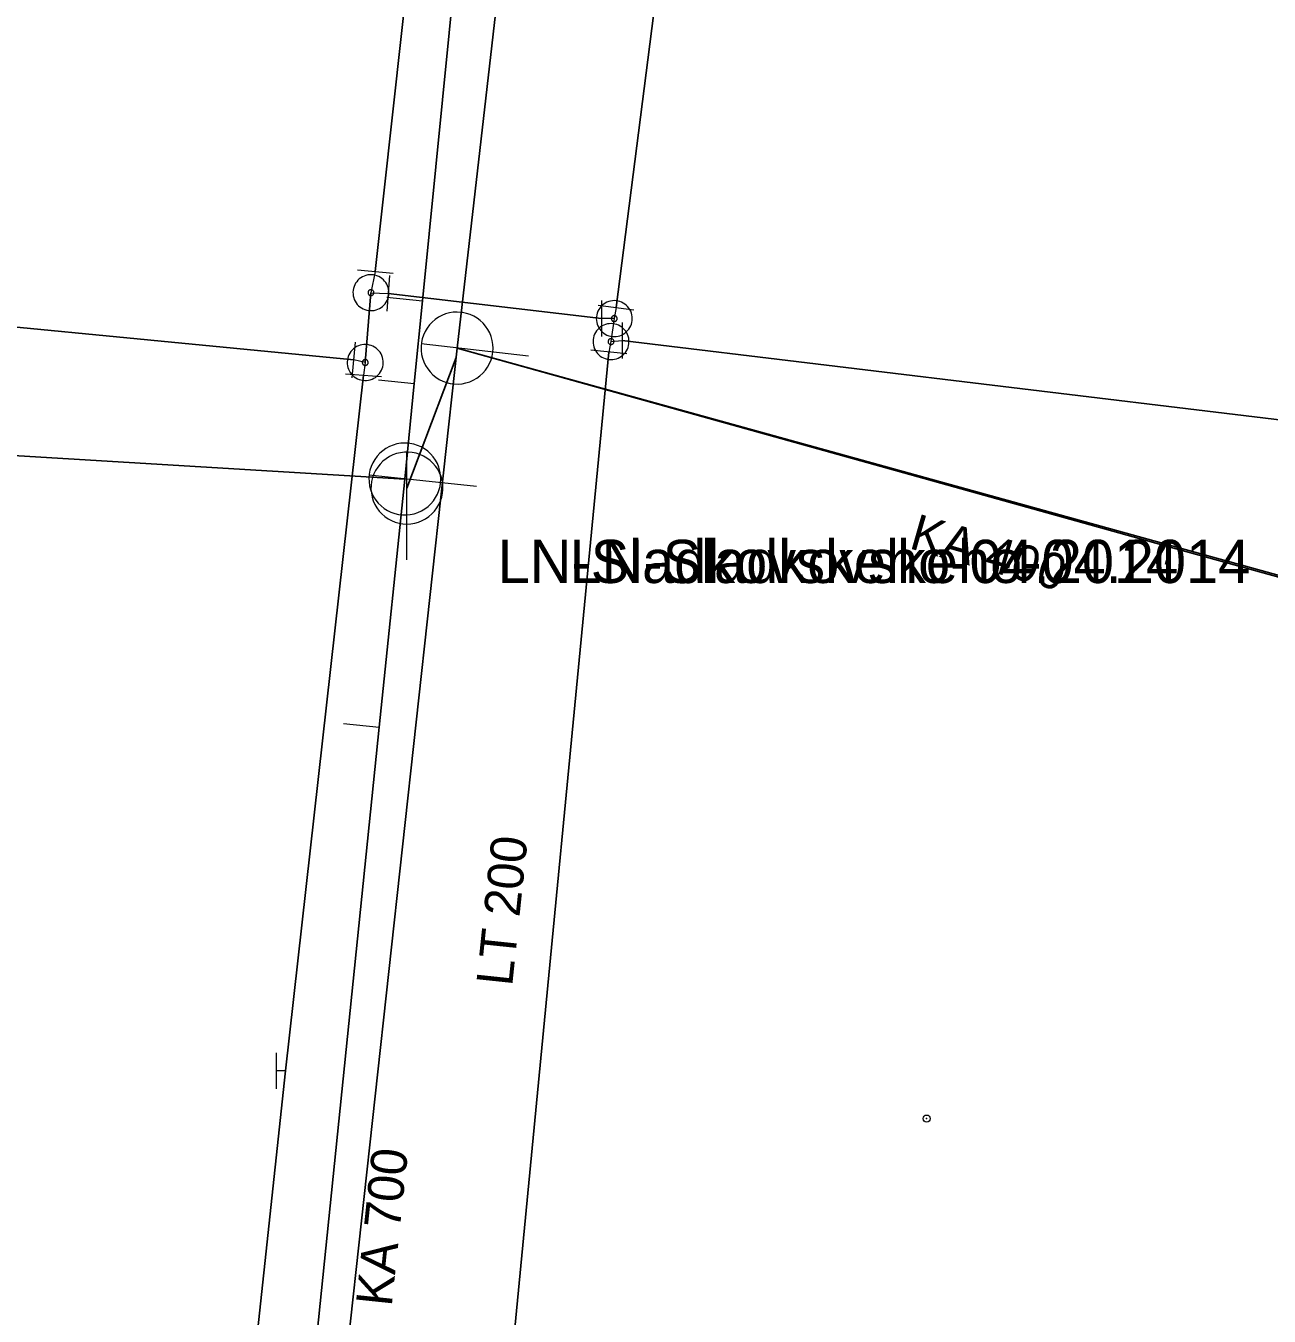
# Model space of a CAD drawing. Extents: x -783064 to -782702, y -1007904 to -1007145.
# Drawn here: x -782810.93 to -782776.38, y -1007591.58 to -1007555.71 of the extents above; entities that cross this region are included whole.
import ezdxf

# ---------------------------------------------------------------- set-up
doc = ezdxf.new("R2010")
doc.units = 0
doc.header["$LTSCALE"] = 0.4
doc.header["$PDMODE"] = 32
doc.header["$PDSIZE"] = 0.2
for name, color, linetype, lineweight in [('1', 7, 'Continuous', 13), ('11', 7, 'Continuous', 13), ('14', 7, 'Continuous', 13), ('17', 7, 'Continuous', 25), ('22', 7, 'Continuous', 13), ('34', 7, 'Continuous', 13), ('47', 7, 'Continuous', 13)]:
    doc.layers.add(name, color=color, linetype=linetype, lineweight=lineweight)

msp = doc.modelspace()

# ---------------------------------------------------------------- linework, layer by layer
at = {"layer": '1'}
msp.add_point((-782785.899, -1007586.089), dxfattribs=at)
at = {"layer": '11'}
for p, q in [((-782800.901, -1007563.255), (-782799.905, -1007563.354)), ((-782801.129, -1007565.554), (-782800.135, -1007565.653)), ((-782779.26, -1007570.68), (-782779.129, -1007570.2)), ((-782802.107, -1007575.109), (-782801.112, -1007575.211))]:
    msp.add_line(p, q, dxfattribs=at)
at = {"layer": '14'}
for p, q in [((-782801.219, -1007562.54), (-782801.34, -1007563.13)), ((-782801.34, -1007563.13), (-782800.859, -1007563.15)), ((-782794.527, -1007563.539), (-782794.579, -1007563.85)), ((-782794.579, -1007563.85), (-782794.93, -1007563.85)), ((-782794.579, -1007563.85), (-782794.67, -1007564.49)), ((-782794.67, -1007564.49), (-782794.73, -1007564.78)), ((-782794.67, -1007564.49), (-782794.359, -1007564.46)), ((-782801.5, -1007565.07), (-782801.82, -1007565)), ((-782801.5, -1007565.07), (-782801.55, -1007565.42)), ((-782803.719, -1007584.76), (-782803.969, -1007584.76))]:
    msp.add_line(p, q, dxfattribs=at)
at = {"layer": '14', "lineweight": 25}
for p, q in [((-782807.829, -1007645.75), (-782798.949, -1007564.67)), ((-782769.09, -1007572.93), (-782798.949, -1007564.67)), ((-782800.34, -1007568.56), (-782798.969, -1007564.93)), ((-782831.579, -1007566.44), (-782800.399, -1007568.31))]:
    msp.add_line(p, q, dxfattribs=at)
for points in [[(-782798.949, -1007564.67), (-782793.087, -1007513.589), (-782789.92, -1007482.8)], [(-782800.399, -1007568.31), (-782800.135, -1007565.653), (-782799.905, -1007563.354), (-782796.375, -1007527.869), (-782796.213, -1007526.237), (-782795.12, -1007515.25)], [(-782767.039, -1007573.57), (-782768.41, -1007573.19), (-782773.26, -1007571.83), (-782779.129, -1007570.2), (-782798.949, -1007564.67)], [(-782804.471, -1007607.979), (-782803.131, -1007594.908), (-782802.837, -1007592.043), (-782801.112, -1007575.211), (-782800.399, -1007568.31)]]:
    msp.add_lwpolyline(points, dxfattribs=at)
at = {"layer": '17'}
for p, q in [((-782801.34, -1007563.13), (-782801.5, -1007565.07)), ((-782794.93, -1007563.85), (-782800.859, -1007563.15)), ((-782794.73, -1007564.78), (-782797.572, -1007594.291))]:
    msp.add_line(p, q, dxfattribs=at)
for points in [[(-782784.199, -1007414.51), (-782788.17, -1007445.88), (-782789.899, -1007459.31), (-782791.09, -1007469.35), (-782793.219, -1007488.27), (-782794.285, -1007499.072), (-782794.78, -1007504.08), (-782795.89, -1007514.14), (-782797.23, -1007526.05), (-782799.52, -1007547.12), (-782801.219, -1007562.54)], [(-782794.527, -1007563.539), (-782793.17, -1007552.95), (-782792.78, -1007548.16), (-782791.739, -1007539.74), (-782790.94, -1007531.25), (-782789.17, -1007514.32), (-782788.309, -1007505.04), (-782787.02, -1007493.25), (-782786.27, -1007487.64), (-782784.98, -1007475.07), (-782783.55, -1007462.11), (-782782.149, -1007449.41), (-782782.032, -1007447.451), (-782779.226, -1007421.176)], [(-782801.82, -1007565), (-782833.557, -1007561.918), (-782847.582, -1007560.556), (-782863.666, -1007558.994), (-782875.35, -1007557.86), (-782891.408, -1007556.103), (-782896.535, -1007556.337)], [(-782721.948, -1007572.833), (-782724.344, -1007572.563), (-782743.599, -1007570.399), (-782747.826, -1007569.923), (-782765.967, -1007567.884), (-782794.359, -1007564.46)], [(-782801.55, -1007565.42), (-782803.719, -1007584.76), (-782806.96, -1007615), (-782809.59, -1007640.17), (-782810.57, -1007649.22)]]:
    msp.add_lwpolyline(points, dxfattribs=at)
at = {"layer": '22'}
for p, q in [((-782796.961, -1007564.897), (-782799.942, -1007564.556)), ((-782800.34, -1007570.56), (-782800.339, -1007567.56)), ((-782798.409, -1007568.515), (-782801.393, -1007568.207))]:
    msp.add_line(p, q, dxfattribs=at)
for points in [[(-782798.834, -1007563.676), (-782798.943, -1007563.67), (-782799.053, -1007563.675), (-782799.161, -1007563.693), (-782799.266, -1007563.721), (-782799.369, -1007563.762), (-782799.465, -1007563.813), (-782799.556, -1007563.875), (-782799.638, -1007563.946), (-782799.714, -1007564.026), (-782799.779, -1007564.113), (-782799.835, -1007564.208), (-782799.88, -1007564.308), (-782799.914, -1007564.412), (-782799.936, -1007564.519), (-782799.947, -1007564.629), (-782799.945, -1007564.738), (-782799.933, -1007564.847), (-782799.907, -1007564.953), (-782799.87, -1007565.056), (-782799.823, -1007565.154), (-782799.764, -1007565.248), (-782799.696, -1007565.333), (-782799.619, -1007565.411), (-782799.534, -1007565.48), (-782799.442, -1007565.539), (-782799.344, -1007565.587), (-782799.241, -1007565.625), (-782799.135, -1007565.652), (-782799.026, -1007565.666), (-782798.916, -1007565.669), (-782798.808, -1007565.66), (-782798.701, -1007565.638), (-782798.596, -1007565.606), (-782798.496, -1007565.562), (-782798.401, -1007565.506), (-782798.313, -1007565.442), (-782798.232, -1007565.368), (-782798.16, -1007565.285), (-782798.097, -1007565.196), (-782798.045, -1007565.099), (-782798.003, -1007564.998), (-782797.973, -1007564.893), (-782797.955, -1007564.784), (-782797.948, -1007564.675), (-782797.954, -1007564.566), (-782797.971, -1007564.458), (-782798, -1007564.352), (-782798.04, -1007564.25), (-782798.092, -1007564.154), (-782798.153, -1007564.063), (-782798.224, -1007563.979), (-782798.304, -1007563.905), (-782798.391, -1007563.839), (-782798.485, -1007563.783), (-782798.585, -1007563.738), (-782798.689, -1007563.704), (-782798.797, -1007563.681)], [(-782800.295, -1007567.315), (-782800.404, -1007567.31), (-782800.514, -1007567.316), (-782800.622, -1007567.335), (-782800.727, -1007567.365), (-782800.829, -1007567.407), (-782800.924, -1007567.459), (-782801.014, -1007567.522), (-782801.096, -1007567.594), (-782801.171, -1007567.675), (-782801.235, -1007567.763), (-782801.29, -1007567.858), (-782801.334, -1007567.959), (-782801.367, -1007568.063), (-782801.388, -1007568.17), (-782801.397, -1007568.28), (-782801.394, -1007568.389), (-782801.381, -1007568.498), (-782801.354, -1007568.604), (-782801.316, -1007568.706), (-782801.267, -1007568.804), (-782801.208, -1007568.897), (-782801.139, -1007568.981), (-782801.06, -1007569.059), (-782800.975, -1007569.127), (-782800.882, -1007569.184), (-782800.784, -1007569.232), (-782800.68, -1007569.269), (-782800.574, -1007569.294), (-782800.465, -1007569.307), (-782800.355, -1007569.308), (-782800.247, -1007569.298), (-782800.14, -1007569.275), (-782800.036, -1007569.242), (-782799.936, -1007569.197), (-782799.841, -1007569.14), (-782799.754, -1007569.075), (-782799.674, -1007569), (-782799.603, -1007568.916), (-782799.542, -1007568.826), (-782799.49, -1007568.729), (-782799.45, -1007568.628), (-782799.421, -1007568.522), (-782799.403, -1007568.413), (-782799.398, -1007568.304), (-782799.405, -1007568.195), (-782799.423, -1007568.087), (-782799.453, -1007567.982), (-782799.495, -1007567.88), (-782799.548, -1007567.784), (-782799.61, -1007567.694), (-782799.682, -1007567.611), (-782799.762, -1007567.538), (-782799.85, -1007567.472), (-782799.945, -1007567.418), (-782800.045, -1007567.374), (-782800.15, -1007567.341), (-782800.258, -1007567.32)], [(-782799.34, -1007568.56), (-782799.345, -1007568.451), (-782799.363, -1007568.343), (-782799.393, -1007568.237), (-782799.433, -1007568.136), (-782799.485, -1007568.039), (-782799.547, -1007567.949), (-782799.619, -1007567.866), (-782799.699, -1007567.792), (-782799.787, -1007567.726), (-782799.881, -1007567.671), (-782799.981, -1007567.626), (-782800.086, -1007567.593), (-782800.193, -1007567.571), (-782800.302, -1007567.561), (-782800.412, -1007567.563), (-782800.52, -1007567.577), (-782800.627, -1007567.602), (-782800.73, -1007567.639), (-782800.828, -1007567.688), (-782800.92, -1007567.746), (-782801.006, -1007567.815), (-782801.083, -1007567.892), (-782801.152, -1007567.978), (-782801.211, -1007568.07), (-782801.259, -1007568.168), (-782801.296, -1007568.271), (-782801.322, -1007568.378), (-782801.336, -1007568.486), (-782801.339, -1007568.596), (-782801.329, -1007568.705), (-782801.308, -1007568.812), (-782801.274, -1007568.916), (-782801.23, -1007569.016), (-782801.175, -1007569.111), (-782801.109, -1007569.199), (-782801.035, -1007569.279), (-782800.952, -1007569.351), (-782800.862, -1007569.413), (-782800.766, -1007569.465), (-782800.664, -1007569.506), (-782800.559, -1007569.536), (-782800.451, -1007569.554), (-782800.341, -1007569.56), (-782800.232, -1007569.554), (-782800.124, -1007569.536), (-782800.019, -1007569.507), (-782799.917, -1007569.466), (-782799.82, -1007569.414), (-782799.73, -1007569.352), (-782799.647, -1007569.281), (-782799.572, -1007569.201), (-782799.507, -1007569.113), (-782799.451, -1007569.019), (-782799.407, -1007568.919), (-782799.373, -1007568.815), (-782799.351, -1007568.707), (-782799.341, -1007568.598)]]:
    msp.add_lwpolyline(points, close=True, dxfattribs=at)
at = {"layer": '34'}
for p, q in [((-782801.717, -1007562.495), (-782800.721, -1007562.585)), ((-782800.823, -1007562.651), (-782800.895, -1007563.648)), ((-782794.93, -1007563.35), (-782794.93, -1007564.35)), ((-782795.022, -1007563.475), (-782794.031, -1007563.603)), ((-782794.359, -1007563.96), (-782794.359, -1007564.96)), ((-782801.864, -1007565.498), (-782801.774, -1007564.502)), ((-782794.232, -1007564.827), (-782795.227, -1007564.731)), ((-782802.048, -1007565.384), (-782801.051, -1007565.456)), ((-782803.968, -1007585.26), (-782803.968, -1007584.26))]:
    msp.add_line(p, q, dxfattribs=at)
at = {"layer": '47'}
for points in [[(-782800.84, -1007563.144), (-782800.841, -1007563.092), (-782800.848, -1007563.04), (-782800.86, -1007562.989), (-782800.877, -1007562.94), (-782800.9, -1007562.892), (-782800.927, -1007562.847), (-782800.959, -1007562.806), (-782800.995, -1007562.768), (-782801.034, -1007562.734), (-782801.077, -1007562.704), (-782801.124, -1007562.678), (-782801.172, -1007562.659), (-782801.222, -1007562.644), (-782801.273, -1007562.634), (-782801.325, -1007562.63), (-782801.377, -1007562.631), (-782801.429, -1007562.638), (-782801.481, -1007562.65), (-782801.529, -1007562.667), (-782801.577, -1007562.69), (-782801.622, -1007562.717), (-782801.664, -1007562.749), (-782801.702, -1007562.785), (-782801.736, -1007562.824), (-782801.765, -1007562.867), (-782801.791, -1007562.914), (-782801.811, -1007562.962), (-782801.825, -1007563.012), (-782801.835, -1007563.063), (-782801.839, -1007563.115), (-782801.838, -1007563.167), (-782801.831, -1007563.219), (-782801.82, -1007563.271), (-782801.802, -1007563.319), (-782801.779, -1007563.367), (-782801.753, -1007563.412), (-782801.721, -1007563.454), (-782801.685, -1007563.492), (-782801.645, -1007563.526), (-782801.602, -1007563.555), (-782801.555, -1007563.581), (-782801.508, -1007563.601), (-782801.457, -1007563.615), (-782801.406, -1007563.625), (-782801.354, -1007563.629), (-782801.302, -1007563.628), (-782801.25, -1007563.621), (-782801.199, -1007563.61), (-782801.15, -1007563.592), (-782801.102, -1007563.569), (-782801.057, -1007563.543), (-782801.016, -1007563.511), (-782800.978, -1007563.475), (-782800.944, -1007563.435), (-782800.914, -1007563.392), (-782800.888, -1007563.345), (-782800.869, -1007563.298), (-782800.854, -1007563.247), (-782800.844, -1007563.196)], [(-782801.258, -1007563.132), (-782801.257, -1007563.123), (-782801.259, -1007563.115), (-782801.261, -1007563.107), (-782801.264, -1007563.099), (-782801.267, -1007563.091), (-782801.272, -1007563.083), (-782801.277, -1007563.076), (-782801.283, -1007563.07), (-782801.29, -1007563.065), (-782801.296, -1007563.06), (-782801.304, -1007563.055), (-782801.312, -1007563.052), (-782801.32, -1007563.05), (-782801.328, -1007563.048), (-782801.337, -1007563.048), (-782801.346, -1007563.047), (-782801.354, -1007563.049), (-782801.362, -1007563.051), (-782801.37, -1007563.054), (-782801.378, -1007563.057), (-782801.386, -1007563.062), (-782801.393, -1007563.067), (-782801.399, -1007563.073), (-782801.405, -1007563.08), (-782801.409, -1007563.086), (-782801.414, -1007563.094), (-782801.417, -1007563.102), (-782801.419, -1007563.11), (-782801.421, -1007563.118), (-782801.421, -1007563.127), (-782801.422, -1007563.136), (-782801.42, -1007563.144), (-782801.418, -1007563.152), (-782801.415, -1007563.16), (-782801.412, -1007563.168), (-782801.408, -1007563.176), (-782801.402, -1007563.183), (-782801.396, -1007563.189), (-782801.389, -1007563.195), (-782801.383, -1007563.199), (-782801.375, -1007563.204), (-782801.367, -1007563.207), (-782801.359, -1007563.209), (-782801.351, -1007563.211), (-782801.342, -1007563.211), (-782801.333, -1007563.212), (-782801.325, -1007563.21), (-782801.317, -1007563.208), (-782801.309, -1007563.205), (-782801.301, -1007563.202), (-782801.293, -1007563.198), (-782801.286, -1007563.192), (-782801.28, -1007563.186), (-782801.275, -1007563.179), (-782801.27, -1007563.173), (-782801.265, -1007563.165), (-782801.262, -1007563.157), (-782801.26, -1007563.149), (-782801.258, -1007563.141)], [(-782794.079, -1007563.85), (-782794.082, -1007563.798), (-782794.09, -1007563.745), (-782794.104, -1007563.696), (-782794.122, -1007563.647), (-782794.146, -1007563.6), (-782794.175, -1007563.556), (-782794.208, -1007563.516), (-782794.245, -1007563.478), (-782794.285, -1007563.446), (-782794.329, -1007563.417), (-782794.376, -1007563.392), (-782794.425, -1007563.375), (-782794.475, -1007563.361), (-782794.527, -1007563.353), (-782794.579, -1007563.35), (-782794.631, -1007563.353), (-782794.683, -1007563.361), (-782794.734, -1007563.375), (-782794.782, -1007563.392), (-782794.829, -1007563.417), (-782794.873, -1007563.446), (-782794.914, -1007563.478), (-782794.951, -1007563.516), (-782794.984, -1007563.556), (-782795.012, -1007563.6), (-782795.036, -1007563.647), (-782795.055, -1007563.696), (-782795.068, -1007563.745), (-782795.076, -1007563.798), (-782795.079, -1007563.85), (-782795.076, -1007563.902), (-782795.068, -1007563.954), (-782795.055, -1007564.005), (-782795.036, -1007564.053), (-782795.012, -1007564.1), (-782794.984, -1007564.144), (-782794.951, -1007564.184), (-782794.914, -1007564.222), (-782794.873, -1007564.255), (-782794.829, -1007564.282), (-782794.782, -1007564.307), (-782794.734, -1007564.326), (-782794.683, -1007564.338), (-782794.631, -1007564.347), (-782794.579, -1007564.35), (-782794.527, -1007564.347), (-782794.475, -1007564.338), (-782794.425, -1007564.326), (-782794.376, -1007564.307), (-782794.329, -1007564.282), (-782794.285, -1007564.255), (-782794.245, -1007564.222), (-782794.208, -1007564.184), (-782794.175, -1007564.144), (-782794.146, -1007564.1), (-782794.122, -1007564.053), (-782794.104, -1007564.005), (-782794.09, -1007563.954), (-782794.082, -1007563.902)], [(-782794.612, -1007563.993), (-782794.664, -1007563.99), (-782794.717, -1007563.992), (-782794.768, -1007564), (-782794.819, -1007564.012), (-782794.868, -1007564.031), (-782794.915, -1007564.054), (-782794.959, -1007564.083), (-782795, -1007564.115), (-782795.037, -1007564.151), (-782795.071, -1007564.191), (-782795.1, -1007564.235), (-782795.124, -1007564.282), (-782795.143, -1007564.33), (-782795.157, -1007564.381), (-782795.166, -1007564.432), (-782795.169, -1007564.484), (-782795.167, -1007564.537), (-782795.159, -1007564.589), (-782795.147, -1007564.639), (-782795.128, -1007564.688), (-782795.105, -1007564.735), (-782795.076, -1007564.78), (-782795.044, -1007564.821), (-782795.008, -1007564.858), (-782794.968, -1007564.891), (-782794.924, -1007564.92), (-782794.877, -1007564.945), (-782794.829, -1007564.963), (-782794.778, -1007564.977), (-782794.727, -1007564.986), (-782794.675, -1007564.989), (-782794.622, -1007564.987), (-782794.57, -1007564.98), (-782794.52, -1007564.967), (-782794.471, -1007564.948), (-782794.424, -1007564.926), (-782794.379, -1007564.897), (-782794.338, -1007564.865), (-782794.301, -1007564.828), (-782794.268, -1007564.788), (-782794.239, -1007564.744), (-782794.214, -1007564.698), (-782794.196, -1007564.649), (-782794.182, -1007564.598), (-782794.173, -1007564.547), (-782794.17, -1007564.495), (-782794.172, -1007564.442), (-782794.179, -1007564.391), (-782794.192, -1007564.34), (-782794.211, -1007564.291), (-782794.233, -1007564.244), (-782794.262, -1007564.2), (-782794.294, -1007564.159), (-782794.331, -1007564.122), (-782794.371, -1007564.088), (-782794.415, -1007564.059), (-782794.461, -1007564.035), (-782794.51, -1007564.016), (-782794.561, -1007564.002)], [(-782794.497, -1007563.85), (-782794.497, -1007563.841), (-782794.499, -1007563.833), (-782794.501, -1007563.825), (-782794.504, -1007563.816), (-782794.508, -1007563.809), (-782794.513, -1007563.802), (-782794.518, -1007563.794), (-782794.524, -1007563.789), (-782794.531, -1007563.784), (-782794.538, -1007563.779), (-782794.546, -1007563.775), (-782794.554, -1007563.772), (-782794.562, -1007563.77), (-782794.57, -1007563.767), (-782794.579, -1007563.767), (-782794.588, -1007563.767), (-782794.596, -1007563.77), (-782794.604, -1007563.772), (-782794.612, -1007563.775), (-782794.62, -1007563.779), (-782794.627, -1007563.784), (-782794.634, -1007563.789), (-782794.64, -1007563.794), (-782794.646, -1007563.802), (-782794.65, -1007563.809), (-782794.654, -1007563.816), (-782794.657, -1007563.825), (-782794.659, -1007563.833), (-782794.661, -1007563.841), (-782794.661, -1007563.85), (-782794.661, -1007563.858), (-782794.659, -1007563.867), (-782794.657, -1007563.875), (-782794.654, -1007563.883), (-782794.65, -1007563.891), (-782794.646, -1007563.897), (-782794.64, -1007563.905), (-782794.634, -1007563.911), (-782794.627, -1007563.917), (-782794.62, -1007563.921), (-782794.612, -1007563.924), (-782794.604, -1007563.928), (-782794.596, -1007563.929), (-782794.588, -1007563.932), (-782794.579, -1007563.932), (-782794.57, -1007563.932), (-782794.562, -1007563.929), (-782794.554, -1007563.928), (-782794.546, -1007563.924), (-782794.538, -1007563.921), (-782794.531, -1007563.917), (-782794.524, -1007563.911), (-782794.518, -1007563.905), (-782794.513, -1007563.897), (-782794.508, -1007563.891), (-782794.504, -1007563.883), (-782794.501, -1007563.875), (-782794.499, -1007563.867), (-782794.497, -1007563.858)], [(-782794.66, -1007564.408), (-782794.669, -1007564.407), (-782794.677, -1007564.408), (-782794.685, -1007564.409), (-782794.694, -1007564.411), (-782794.702, -1007564.414), (-782794.71, -1007564.418), (-782794.717, -1007564.423), (-782794.724, -1007564.428), (-782794.73, -1007564.434), (-782794.735, -1007564.441), (-782794.74, -1007564.448), (-782794.744, -1007564.456), (-782794.747, -1007564.463), (-782794.75, -1007564.471), (-782794.751, -1007564.48), (-782794.752, -1007564.489), (-782794.751, -1007564.497), (-782794.75, -1007564.505), (-782794.748, -1007564.514), (-782794.745, -1007564.522), (-782794.741, -1007564.53), (-782794.736, -1007564.537), (-782794.731, -1007564.544), (-782794.725, -1007564.551), (-782794.718, -1007564.555), (-782794.711, -1007564.56), (-782794.703, -1007564.564), (-782794.696, -1007564.567), (-782794.688, -1007564.57), (-782794.679, -1007564.571), (-782794.67, -1007564.572), (-782794.662, -1007564.571), (-782794.654, -1007564.57), (-782794.645, -1007564.568), (-782794.637, -1007564.565), (-782794.63, -1007564.562), (-782794.622, -1007564.556), (-782794.615, -1007564.551), (-782794.608, -1007564.545), (-782794.604, -1007564.538), (-782794.599, -1007564.531), (-782794.595, -1007564.523), (-782794.592, -1007564.516), (-782794.589, -1007564.508), (-782794.588, -1007564.499), (-782794.587, -1007564.49), (-782794.588, -1007564.482), (-782794.589, -1007564.474), (-782794.591, -1007564.465), (-782794.594, -1007564.457), (-782794.597, -1007564.45), (-782794.603, -1007564.442), (-782794.608, -1007564.435), (-782794.614, -1007564.429), (-782794.621, -1007564.424), (-782794.628, -1007564.419), (-782794.636, -1007564.415), (-782794.643, -1007564.412), (-782794.651, -1007564.409)], [(-782801, -1007565.084), (-782801.001, -1007565.032), (-782801.008, -1007564.98), (-782801.02, -1007564.929), (-782801.037, -1007564.88), (-782801.06, -1007564.832), (-782801.087, -1007564.787), (-782801.119, -1007564.746), (-782801.155, -1007564.708), (-782801.194, -1007564.674), (-782801.237, -1007564.644), (-782801.284, -1007564.618), (-782801.332, -1007564.599), (-782801.382, -1007564.584), (-782801.433, -1007564.574), (-782801.485, -1007564.57), (-782801.537, -1007564.571), (-782801.589, -1007564.578), (-782801.641, -1007564.59), (-782801.689, -1007564.607), (-782801.737, -1007564.63), (-782801.782, -1007564.657), (-782801.824, -1007564.689), (-782801.862, -1007564.725), (-782801.896, -1007564.764), (-782801.925, -1007564.807), (-782801.951, -1007564.854), (-782801.971, -1007564.902), (-782801.985, -1007564.952), (-782801.995, -1007565.003), (-782801.999, -1007565.055), (-782801.998, -1007565.107), (-782801.991, -1007565.159), (-782801.98, -1007565.211), (-782801.962, -1007565.259), (-782801.939, -1007565.307), (-782801.913, -1007565.352), (-782801.881, -1007565.394), (-782801.845, -1007565.432), (-782801.805, -1007565.466), (-782801.762, -1007565.495), (-782801.715, -1007565.521), (-782801.668, -1007565.541), (-782801.617, -1007565.555), (-782801.566, -1007565.565), (-782801.514, -1007565.569), (-782801.462, -1007565.568), (-782801.41, -1007565.561), (-782801.359, -1007565.55), (-782801.31, -1007565.532), (-782801.262, -1007565.509), (-782801.217, -1007565.483), (-782801.176, -1007565.451), (-782801.138, -1007565.415), (-782801.104, -1007565.375), (-782801.074, -1007565.332), (-782801.048, -1007565.285), (-782801.029, -1007565.238), (-782801.014, -1007565.187), (-782801.004, -1007565.136)], [(-782801.418, -1007565.072), (-782801.417, -1007565.063), (-782801.419, -1007565.055), (-782801.421, -1007565.047), (-782801.424, -1007565.039), (-782801.427, -1007565.031), (-782801.432, -1007565.023), (-782801.437, -1007565.016), (-782801.443, -1007565.01), (-782801.45, -1007565.005), (-782801.456, -1007565), (-782801.464, -1007564.995), (-782801.472, -1007564.992), (-782801.48, -1007564.99), (-782801.488, -1007564.988), (-782801.497, -1007564.988), (-782801.506, -1007564.987), (-782801.514, -1007564.989), (-782801.522, -1007564.991), (-782801.53, -1007564.994), (-782801.538, -1007564.997), (-782801.546, -1007565.002), (-782801.553, -1007565.007), (-782801.559, -1007565.013), (-782801.565, -1007565.02), (-782801.569, -1007565.026), (-782801.574, -1007565.034), (-782801.577, -1007565.042), (-782801.579, -1007565.05), (-782801.581, -1007565.058), (-782801.581, -1007565.067), (-782801.582, -1007565.076), (-782801.58, -1007565.084), (-782801.578, -1007565.092), (-782801.575, -1007565.1), (-782801.572, -1007565.108), (-782801.568, -1007565.116), (-782801.562, -1007565.123), (-782801.556, -1007565.129), (-782801.549, -1007565.135), (-782801.543, -1007565.139), (-782801.535, -1007565.144), (-782801.527, -1007565.147), (-782801.519, -1007565.149), (-782801.511, -1007565.151), (-782801.502, -1007565.151), (-782801.493, -1007565.152), (-782801.485, -1007565.15), (-782801.477, -1007565.148), (-782801.469, -1007565.145), (-782801.461, -1007565.142), (-782801.453, -1007565.138), (-782801.446, -1007565.132), (-782801.44, -1007565.126), (-782801.435, -1007565.119), (-782801.43, -1007565.113), (-782801.425, -1007565.105), (-782801.422, -1007565.097), (-782801.42, -1007565.089), (-782801.418, -1007565.081)]]:
    msp.add_lwpolyline(points, close=True, dxfattribs=at)

# ---------------------------------------------------------------- texts
at = {"layer": '1'}
for s, rotation, p in [('KA 400', 344, (-782786.418, -1007570.227)), ('LT 200', 84, (-782797.418, -1007582.427)), ('KA 700', 84, (-782800.765, -1007591.331))]:
    msp.add_text(s, height=1, rotation=rotation, dxfattribs=at).set_placement(p)
for p in [(-782797.82, -1007571.2), (-782795.82, -1007571.2)]:
    msp.add_text('LN-Sladkovskeho-04.2014 ', height=1.2, dxfattribs=at).set_placement(p)

doc.saveas('drawing.dxf')
